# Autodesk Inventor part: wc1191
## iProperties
Shininess: 64.0
Length Units: 11272
Angle Units: 11279
Time Units: 11290
Mass Units: 11286
Length Display Precision: 3
Angle Display Precision: 2
Compacted: True
Part Number: wc1191
Document SubType Name: Modeling
Created: 2004-08
Designer: John Blackburn
Manufacturer: Standard
Standards Organization: Custom
Material: Phenolic
Density: 0.0
Volumn: 0.0
Area: 0.0
PropertySet Name: Model Information
Control State: 0
Master: False
Checked Out: False
Author: John Blackburn
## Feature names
1. Revolution1
